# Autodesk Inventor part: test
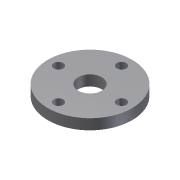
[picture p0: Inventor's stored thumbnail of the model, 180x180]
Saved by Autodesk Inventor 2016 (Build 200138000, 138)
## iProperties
Shininess: 65.0
Angle Display Precision: 2
Document Length Units: 11269
Document Angle Units: 11279
Document Time Units: 11290
Document Mass Units: 11283
Document Length Units Precision: 3
Document Angle Units Precision: 2
Created: 2002-02
Part Number: test
Document SubType Name: Modeling
Designer: ***
Density: 1 g/cm^3
Material: Generic
Appearance: Default
Density: 0.0
Volumn: 0.0
Area: 0.0
PropertySet Name: Model Information
Control State: 0
Master: False
Checked Out: False
Author: ***
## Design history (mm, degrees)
sketch "Sketch1"
  geometry: C1 r 100 at (0, 0); C2 r 28 at (0, 0)
  constraints: 2 centre point, 1 coincident
  dimensions: "d0" = 200 diameter of C1; "d1" = 56 diameter of C2
extrude "Extrusion1" new body sketch "Sketch1" stored distance "d2" = 25; taper "d3" = 0 deg
sketch "Sketch2"
  geometry: 2 further points
  dimensions: "d4" = 75 distance of point (0, 0) point (-75, 0)
hole "Hole1" sketch "Sketch2" at (-75, 0) diameter "d5" = 22.3; stored, may be unused: countersink angle "d9" = 82 deg, drill point angle "d11" = 118 deg; dims "d6" = 6, "d7" = 4, "d8" = 2, "d10" = 8
pattern_circular "Circular Pattern1" dims angle "d14" = 360 deg
body "Solid1"
